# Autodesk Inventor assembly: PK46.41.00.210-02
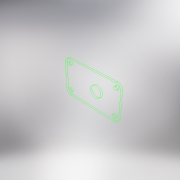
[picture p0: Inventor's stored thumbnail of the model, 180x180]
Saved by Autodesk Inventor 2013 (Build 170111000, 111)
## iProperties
Created: 2012-02
Part Number: PK46.41.00.210-02
Document SubType Name: Weldment
Designer: tedescj
Weld Material: Welded Aluminum-6061
Author: tedescj
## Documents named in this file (5)
- D:\FrontLoaderVault\Data\Assy, Chassis, Front\PK46.41.00.210-02.iam
- D:\FrontLoaderVault\Data\Assy, Chassis, Front\PK46.41.00.0111.ipt
- D:\FrontLoaderVault\Data\Assy, Chassis, Front\PK46.41.00.012-02.ipt
- D:\FrontLoaderVault\Data\Assy, Chassis, Front\PK46.41.00.011-02.ipt
- D:\FrontLoaderVault\Data\Assy, Chassis, Front\PK46.41.00.013.ipt
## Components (4 placed, 4 different names)
1. PK46.41.00.0111:1 — Mate:2
2. PK46.41.00.012-02:1
3. PK46.41.00.011-02:1
4. PK46.41.00.013:1 — Flush:1, Mate:1, Mate:2
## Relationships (3: Mate 2, Flush 1)
- Flush:1: PK46.41.00.013:1
- Mate:1: PK46.41.00.013:1
- Mate:2: PK46.41.00.0111:1 ↔ PK46.41.00.013:1
